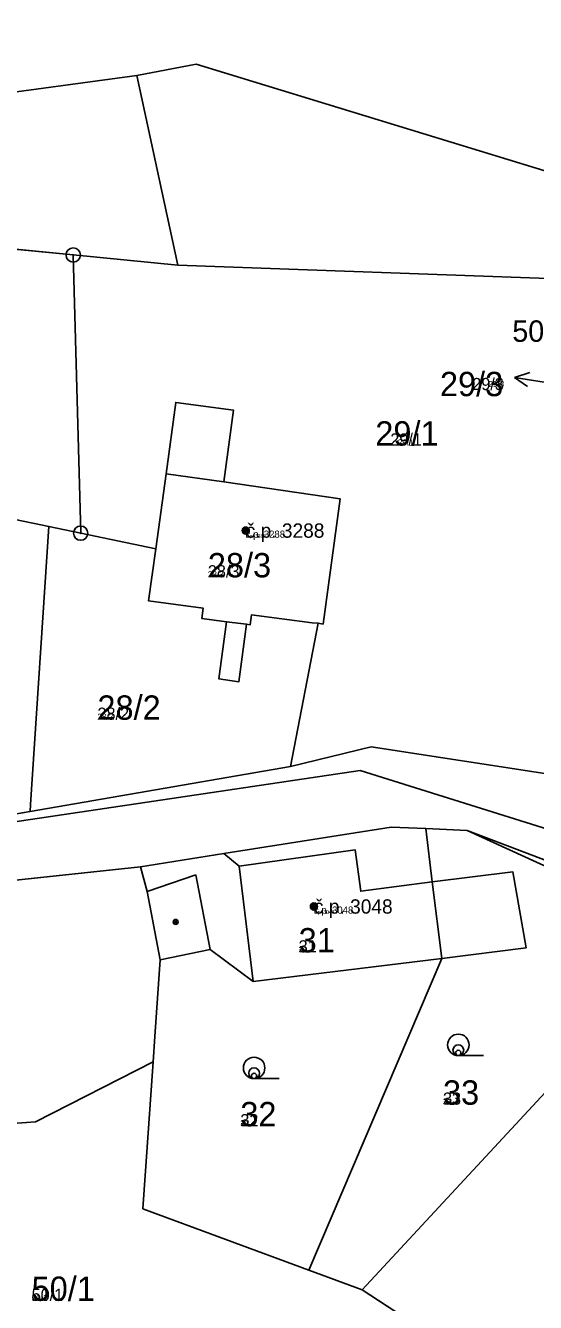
# Model space of a CAD drawing. Extents: x -759873 to -758487, y -975024 to -973516.
# Drawn here: x -759190.5 to -759154.9, y -974296.3 to -974207.1 of the extents above; entities that cross this region are included whole.
import ezdxf

# ---------------------------------------------------------------- set-up
doc = ezdxf.new("R2010")
doc.units = 0
for name, color, linetype in [('KAT_02_hranice parcel', 7, 'Continuous'), ('KAT_03_1000_st čísla parcelní', 7, 'Continuous'), ('KAT_03_1000_čísla parcelní', 7, 'Continuous'), ('KAT_03_1000_čísla popisná', 7, 'Continuous'), ('KAT_03_250_st čísla parcelní', 7, 'Continuous'), ('KAT_03_250_čísla parcelní', 7, 'Continuous'), ('KAT_03_250_čísla popisná', 7, 'Continuous'), ('KAT_03_500_st čísla parcelní', 7, 'Continuous'), ('KAT_03_500_čísla parcelní', 7, 'Continuous'), ('KAT_03_500_čísla popisná', 7, 'Continuous'), ('KAT_04_vnitřní kresba', 7, 'Continuous'), ('KAT_05_1000_značky kultur', 7, 'Continuous'), ('KAT_05_250_značky kultur', 7, 'Continuous'), ('KAT_05_500_značky kultur', 7, 'Continuous'), ('KAT_07_1000_značky budov', 7, 'Continuous'), ('KAT_07_250_značky budov', 7, 'Continuous'), ('KAT_07_500_značky budov', 7, 'Continuous'), ('KAT_11_značky bodu BP', 7, 'Continuous'), ('KAT_12_pomocná šipka', 7, 'Continuous'), ('KAT_14_plocha_budovy', 7, 'Continuous'), ('KAT_14_plocha_pozemek', 7, 'Continuous')]:
    doc.layers.add(name, color=color, linetype=linetype)

msp = doc.modelspace()

# ---------------------------------------------------------------- linework, layer by layer
at = {"layer": 'KAT_02_hranice parcel'}
for p, q in [((-759208.98, -974220.98), (-759187.17, -974223.14)), ((-759187.17, -974223.14), (-759186.65, -974242.58)), ((-759186.65, -974242.58), (-759188.88, -974242.12)), ((-759181.4, -974243.68), (-759186.65, -974242.58)), ((-759171.99, -974258.88), (-759170.05, -974248.88)), ((-759190.18, -974262.03), (-759171.99, -974258.88)), ((-759212.16, -974265.84), (-759190.18, -974262.03)), ((-759182.46, -974265.89), (-759228.43, -974270.82)), ((-759170.69, -974294.08), (-759161.41, -974272.3)), ((-759166.96, -974295.46), (-759153.27, -974280.7)), ((-759170.69, -974294.08), (-759166.96, -974295.46)), ((-759166.96, -974295.46), (-759146.69, -974308.69))]:
    msp.add_line(p, q, dxfattribs=at)
for points in [[(-759187.17, -974223.14), (-759179.86, -974223.86), (-759152.65, -974224.82), (-759152.43, -974225.07)], [(-759170.05, -974248.88), (-759169.7, -974248.93), (-759168.51, -974240.17), (-759176.63, -974238.99), (-759175.96, -974233.99), (-759180, -974233.44), (-759180.68, -974238.44), (-759181.4, -974243.68)], [(-759188.88, -974242.12), (-759198.87, -974240.04), (-759208.48, -974239.47)], [(-759190.18, -974262.03), (-759190.15, -974261.54), (-759188.88, -974242.12)], [(-759170.05, -974248.88), (-759170.47, -974248.85), (-759174.7, -974248.28), (-759174.8, -974248.99), (-759175.05, -974248.95), (-759175.59, -974252.96), (-759176.99, -974252.77), (-759176.45, -974248.77), (-759178.18, -974248.54), (-759178.08, -974247.83), (-759181.9, -974247.32), (-759181.4, -974243.68)], [(-759153.59, -974259.47), (-759166.35, -974257.52), (-759171.99, -974258.88)], [(-759162.53, -974263.23), (-759164.95, -974263.13), (-759176.65, -974264.97), (-759182.46, -974265.89)], [(-759161.41, -974272.3), (-759155.51, -974271.57), (-759156.44, -974266.24), (-759162.07, -974266.94), (-759162.53, -974263.23)], [(-759148.86, -974268.28), (-759159.62, -974263.35), (-759162.53, -974263.23)], [(-759181.09, -974272.39), (-759182, -974267.63), (-759182.46, -974265.89)], [(-759228.43, -974270.82), (-759227.24, -974274.32), (-759215.95, -974278.9), (-759208.4, -974281.61), (-759195.89, -974284.15), (-759189.8, -974283.73), (-759181.58, -974279.53)], [(-759181.58, -974279.53), (-759181.46, -974277.76), (-759181.09, -974272.39)], [(-759181.09, -974272.39), (-759177.6, -974271.67), (-759174.58, -974273.92), (-759161.41, -974272.3)], [(-759181.58, -974279.53), (-759182.3, -974289.79), (-759170.69, -974294.08)]]:
    msp.add_lwpolyline(points, dxfattribs=at)
at = {"layer": 'KAT_03_1000_čísla popisná'}
for centre in [(-759175.11, -974242.4), (-759170.34, -974268.67)]:
    msp.add_circle(centre, 0.25, dxfattribs=at)
at = {"layer": 'KAT_03_250_čísla popisná'}
for centre in [(-759175.11, -974242.4), (-759170.34, -974268.67)]:
    msp.add_circle(centre, 0.0625, dxfattribs=at)
at = {"layer": 'KAT_03_500_čísla popisná'}
for centre in [(-759175.11, -974242.4), (-759170.34, -974268.67)]:
    msp.add_circle(centre, 0.125, dxfattribs=at)
at = {"layer": 'KAT_04_vnitřní kresba'}
for p, q in [((-759182.72, -974210.6), (-759178.58, -974209.8)), ((-759178.58, -974209.8), (-759149.27, -974218.77)), ((-759210.71, -974214.36), (-759182.72, -974210.6)), ((-759182.72, -974210.6), (-759179.86, -974223.86)), ((-759180.68, -974238.44), (-759176.63, -974238.99)), ((-759176.45, -974248.77), (-759175.05, -974248.95)), ((-759212.16, -974265.84), (-759167.11, -974259.17)), ((-759167.11, -974259.17), (-759144.31, -974266.29)), ((-759159.62, -974263.35), (-759148.47, -974267.61)), ((-759176.65, -974264.97), (-759175.57, -974265.86)), ((-759175.57, -974265.86), (-759167.47, -974264.71)), ((-759167.47, -974264.71), (-759167.07, -974267.6)), ((-759175.57, -974265.86), (-759174.58, -974273.92)), ((-759182, -974267.63), (-759178.61, -974266.46)), ((-759178.61, -974266.46), (-759177.6, -974271.67)), ((-759167.07, -974267.6), (-759162.07, -974266.94)), ((-759162.07, -974266.94), (-759161.41, -974272.3))]:
    msp.add_line(p, q, dxfattribs=at)
at = {"layer": 'KAT_05_1000_značky kultur'}
for p, q in [((-759160.243, -974279.09), (-759158.493, -974279.09)), ((-759174.523, -974280.7), (-759172.773, -974280.7))]:
    msp.add_line(p, q, dxfattribs=at)
for centre in [(-759160.243, -974278.34), (-759174.523, -974279.95)]:
    msp.add_circle(centre, 0.75, dxfattribs=at)
at = {"layer": 'KAT_05_250_značky kultur'}
for p, q in [((-759160.248, -974279.09), (-759159.811, -974279.09)), ((-759174.528, -974280.7), (-759174.091, -974280.7))]:
    msp.add_line(p, q, dxfattribs=at)
for centre in [(-759160.248, -974278.902), (-759174.528, -974280.512)]:
    msp.add_circle(centre, 0.187, dxfattribs=at)
at = {"layer": 'KAT_05_500_značky kultur'}
for p, q in [((-759160.247, -974279.09), (-759159.372, -974279.09)), ((-759174.527, -974280.7), (-759173.652, -974280.7))]:
    msp.add_line(p, q, dxfattribs=at)
for centre in [(-759160.246, -974278.715), (-759174.526, -974280.325)]:
    msp.add_circle(centre, 0.375, dxfattribs=at)
at = {"layer": 'KAT_07_1000_značky budov'}
for centre in [(-759175.117, -974242.399), (-759170.347, -974268.669), (-759180.007, -974269.749)]:
    msp.add_circle(centre, 0.175, dxfattribs=at)
at = {"layer": 'KAT_07_250_značky budov'}
for centre in [(-759175.112, -974242.4), (-759170.342, -974268.67), (-759180.002, -974269.75)]:
    msp.add_circle(centre, 0.0437, dxfattribs=at)
at = {"layer": 'KAT_07_500_značky budov'}
for centre in [(-759175.113, -974242.4), (-759170.343, -974268.67), (-759180.003, -974269.75)]:
    msp.add_circle(centre, 0.0875, dxfattribs=at)
at = {"layer": 'KAT_11_značky bodu BP'}
for centre, radius in [((-759187.17, -974223.14), 0.5), ((-759187.17, -974223.14), 0.0303), ((-759186.65, -974242.58), 0.5), ((-759186.65, -974242.58), 0.0303)]:
    msp.add_circle(centre, radius, dxfattribs=at)
at = {"layer": 'KAT_12_pomocná šipka'}
for p, q in [((-759156.314, -974231.691), (-759155.247, -974231.353)), ((-759153.35, -974232.16), (-759156.314, -974231.691)), ((-759156.314, -974231.691), (-759155.403, -974232.342))]:
    msp.add_line(p, q, dxfattribs=at)
at = {"layer": 'KAT_14_plocha_budovy'}
for points in [[(-759174.7, -974248.28), (-759170.47, -974248.85), (-759170.05, -974248.88), (-759169.7, -974248.93), (-759168.51, -974240.17), (-759176.63, -974238.99), (-759180.68, -974238.44), (-759181.4, -974243.68), (-759181.9, -974247.32), (-759178.08, -974247.83), (-759178.18, -974248.54), (-759176.45, -974248.77), (-759175.05, -974248.95), (-759174.8, -974248.99)], [(-759174.58, -974273.92), (-759161.41, -974272.3), (-759162.07, -974266.94), (-759167.07, -974267.6), (-759167.47, -974264.71), (-759175.57, -974265.86)]]:
    msp.add_lwpolyline(points, close=True, dxfattribs=at)
at = {"layer": 'KAT_14_plocha_pozemek'}
for points in [[(-759208.98, -974220.98), (-759187.17, -974223.14), (-759179.86, -974223.86), (-759152.65, -974224.82), (-759152.43, -974225.07), (-759148.36, -974224.76), (-759133.61, -974225.4), (-759129.65, -974225.67), (-759118.11, -974227.12), (-759102.76, -974233.33), (-759082.54, -974240.13), (-759086.34, -974224.22), (-759091.94, -974200.78), (-759089.9, -974172.96), (-759085.8, -974168.68), (-759080.44, -974126.48), (-759059.17, -974102.77), (-759054.16, -974081.34), (-759050.16, -974065.96), (-759040.87, -974035.88)], [(-759090.1, -974313.42), (-759098.18, -974304.42), (-759106.6, -974295.05), (-759109.41, -974292.79), (-759130.63, -974274.73), (-759134.45, -974270.58), (-759142.01, -974265.12), (-759153.59, -974259.47), (-759166.35, -974257.52), (-759171.99, -974258.88), (-759190.18, -974262.03), (-759212.16, -974265.84)], [(-759228.43, -974270.82), (-759182.46, -974265.89), (-759176.65, -974264.97), (-759164.95, -974263.13), (-759162.53, -974263.23), (-759159.62, -974263.35), (-759148.86, -974268.28), (-759137.55, -974276.08), (-759137.41, -974276.19), (-759133.42, -974279.5), (-759126.27, -974285.42), (-759121.65, -974289.25), (-759113.88, -974295.69), (-759108.36, -974300.77), (-759091.71, -974319.84), (-759079.48, -974333.82), (-759074.99, -974338.96), (-759070.5, -974344.1), (-759060.98, -974351.22), (-759051.14, -974355.72), (-759039.97, -974358.1), (-759037.67, -974358.59), (-759031.63, -974358.94), (-758978.01, -974362.06)], [(-759146.69, -974308.69), (-759166.96, -974295.46), (-759170.69, -974294.08), (-759182.3, -974289.79), (-759181.58, -974279.53), (-759189.8, -974283.73), (-759195.89, -974284.15)]]:
    msp.add_lwpolyline(points, dxfattribs=at)
for points in [[(-759208.98, -974220.98), (-759208.48, -974239.47), (-759198.87, -974240.04), (-759188.88, -974242.12), (-759186.65, -974242.58), (-759187.17, -974223.14)], [(-759153.96, -974236.59), (-759153.88, -974228.7), (-759152.43, -974225.07), (-759152.65, -974224.82), (-759179.86, -974223.86), (-759187.17, -974223.14), (-759186.65, -974242.58), (-759181.4, -974243.68), (-759180.68, -974238.44), (-759180, -974233.44), (-759175.96, -974233.99), (-759176.63, -974238.99), (-759168.51, -974240.17), (-759169.7, -974248.93), (-759170.05, -974248.88), (-759171.99, -974258.88), (-759166.35, -974257.52), (-759153.59, -974259.47), (-759152.59, -974239.28)], [(-759180, -974233.44), (-759180.68, -974238.44), (-759181.4, -974243.68), (-759181.9, -974247.32), (-759178.08, -974247.83), (-759178.18, -974248.54), (-759176.45, -974248.77), (-759176.99, -974252.77), (-759175.59, -974252.96), (-759175.05, -974248.95), (-759174.8, -974248.99), (-759174.7, -974248.28), (-759170.47, -974248.85), (-759170.05, -974248.88), (-759169.7, -974248.93), (-759168.51, -974240.17), (-759176.63, -974238.99), (-759175.96, -974233.99)], [(-759198.87, -974240.04), (-759208.48, -974239.47), (-759211.38, -974251.03), (-759211.61, -974262.52), (-759212.16, -974265.84), (-759190.18, -974262.03), (-759190.15, -974261.54), (-759188.88, -974242.12)], [(-759170.05, -974248.88), (-759170.47, -974248.85), (-759174.7, -974248.28), (-759174.8, -974248.99), (-759175.05, -974248.95), (-759175.59, -974252.96), (-759176.99, -974252.77), (-759176.45, -974248.77), (-759178.18, -974248.54), (-759178.08, -974247.83), (-759181.9, -974247.32), (-759181.4, -974243.68), (-759186.65, -974242.58), (-759188.88, -974242.12), (-759190.15, -974261.54), (-759190.18, -974262.03), (-759171.99, -974258.88)], [(-759177.6, -974271.67), (-759174.58, -974273.92), (-759161.41, -974272.3), (-759155.51, -974271.57), (-759156.44, -974266.24), (-759162.07, -974266.94), (-759162.53, -974263.23), (-759164.95, -974263.13), (-759176.65, -974264.97), (-759182.46, -974265.89), (-759182, -974267.63), (-759181.09, -974272.39)], [(-759159.62, -974263.35), (-759162.53, -974263.23), (-759162.07, -974266.94), (-759156.44, -974266.24), (-759155.51, -974271.57), (-759161.41, -974272.3), (-759170.69, -974294.08), (-759166.96, -974295.46), (-759153.27, -974280.7), (-759148.86, -974268.28)], [(-759195.89, -974284.15), (-759189.8, -974283.73), (-759181.58, -974279.53), (-759181.46, -974277.76), (-759181.09, -974272.39), (-759182, -974267.63), (-759182.46, -974265.89), (-759228.43, -974270.82), (-759227.24, -974274.32), (-759215.95, -974278.9), (-759208.4, -974281.61)], [(-759170.69, -974294.08), (-759161.41, -974272.3), (-759174.58, -974273.92), (-759177.6, -974271.67), (-759181.09, -974272.39), (-759181.46, -974277.76), (-759181.58, -974279.53), (-759182.3, -974289.79)], [(-759146.69, -974308.69), (-759140.38, -974309.09), (-759114.55, -974297.73), (-759113.88, -974295.69), (-759121.65, -974289.25), (-759127.52, -974296.12), (-759132.15, -974292.31), (-759135.42, -974296.13), (-759140.96, -974291.39), (-759139.65, -974289.86), (-759144.55, -974286.05), (-759142.65, -974283.61), (-759143.3, -974283.11), (-759153.27, -974280.7), (-759166.96, -974295.46)]]:
    msp.add_lwpolyline(points, close=True, dxfattribs=at)

# ---------------------------------------------------------------- texts
at = {"layer": 'KAT_03_1000_st čísla parcelní'}
for s, p in [('28/3', (-759177.76, -974245.669)), ('28/2', (-759185.48, -974255.62)), ('31', (-759171.41, -974271.88))]:
    msp.add_text(s, height=1.7, dxfattribs=at).set_placement(p)
at = {"layer": 'KAT_03_1000_čísla parcelní'}
for s, p in [('29/3', (-759161.532, -974233.006)), ('29/1', (-759166.051, -974236.46)), ('33', (-759161.32, -974282.52)), ('32', (-759175.49, -974284.03)), ('50/1', (-759190.08, -974296.23))]:
    msp.add_text(s, height=1.7, dxfattribs=at).set_placement(p)
at = {"layer": 'KAT_03_1000_čísla popisná'}
for s, p in [('č.p. 3288', (-759175.11, -974242.9)), ('č.p. 3048', (-759170.34, -974269.17))]:
    msp.add_text(s, height=1, dxfattribs=at).set_placement(p)
at = {"layer": 'KAT_03_250_st čísla parcelní'}
for s, p in [('28/3', (-759177.76, -974245.669)), ('28/2', (-759185.48, -974255.62)), ('31', (-759171.41, -974271.88))]:
    msp.add_text(s, height=0.425, dxfattribs=at).set_placement(p)
at = {"layer": 'KAT_03_250_čísla parcelní'}
for s, p in [('29/3', (-759158.147, -974232.369)), ('29/1', (-759164.482, -974236.46)), ('33', (-759161.32, -974282.52)), ('32', (-759175.49, -974284.03)), ('50/1', (-759190.08, -974296.23))]:
    msp.add_text(s, height=0.425, dxfattribs=at).set_placement(p)
at = {"layer": 'KAT_03_250_čísla popisná'}
for s, p in [('č.p. 3288', (-759175.11, -974242.9)), ('č.p. 3048', (-759170.34, -974269.17))]:
    msp.add_text(s, height=0.25, dxfattribs=at).set_placement(p)
at = {"layer": 'KAT_03_500_st čísla parcelní'}
for s, p in [('28/3', (-759177.76, -974245.669)), ('28/2', (-759185.48, -974255.62)), ('31', (-759171.41, -974271.88))]:
    msp.add_text(s, height=0.85, dxfattribs=at).set_placement(p)
at = {"layer": 'KAT_03_500_čísla parcelní'}
for s, p in [('29/3', (-759159.275, -974232.581)), ('29/1', (-759165.005, -974236.46)), ('33', (-759161.32, -974282.52)), ('32', (-759175.49, -974284.03)), ('50/1', (-759190.08, -974296.23))]:
    msp.add_text(s, height=0.85, dxfattribs=at).set_placement(p)
at = {"layer": 'KAT_03_500_čísla popisná'}
for s, p in [('č.p. 3288', (-759175.11, -974242.9)), ('č.p. 3048', (-759170.34, -974269.17))]:
    msp.add_text(s, height=0.5, dxfattribs=at).set_placement(p)
at = {"layer": 'KAT_11_značky bodu BP'}
msp.add_text('504', height=1.5, dxfattribs=at).set_placement((-759156.473, -974229.21))

doc.saveas('drawing.dxf')
